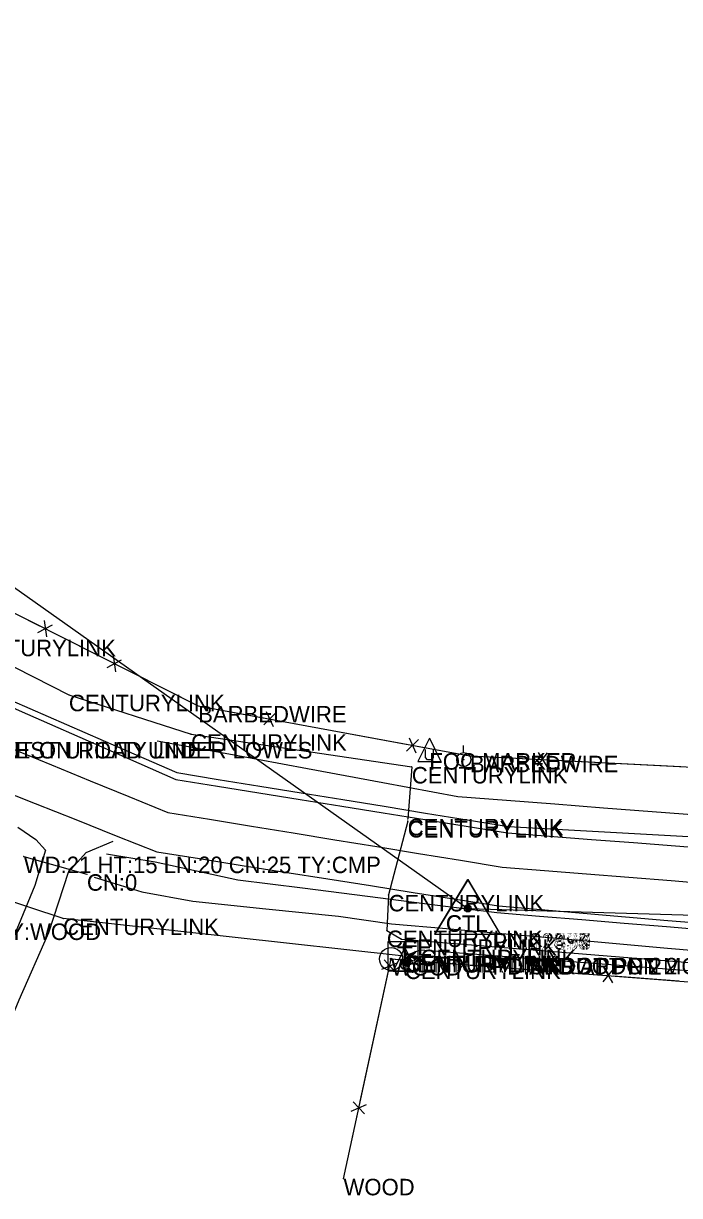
# Model space of a CAD drawing. Extents: x 675481 to 678499, y 212715 to 215285.
# Drawn here: x 675753.3 to 675952.1, y 214646.6 to 215001.7 of the extents above; entities that cross this region are included whole.
import ezdxf

# ---------------------------------------------------------------- set-up
doc = ezdxf.new("R2010")
doc.units = 0
for name, color, linetype in [('S_BASELINE', 7, 'Continuous'), ('S_DITCHLINE', 7, 'Continuous'), ('S_DRG_PT_SYM', 7, 'Continuous'), ('S_DRIVEWAY', 7, 'Continuous'), ('S_EDGE_PAVEMENT', 7, 'Continuous'), ('S_ELECTRIC_UTILITIES_ANNOT', 7, 'Continuous'), ('S_FENCE', 7, 'Continuous'), ('S_FENCE_ANNOT', 7, 'Continuous'), ('S_FIBER_OPTIC_CABLE', 7, 'Continuous'), ('S_FIBER_OPTIC_CABLE_ANNOT', 7, 'Continuous'), ('S_MSC_PT_SYM', 7, 'Continuous'), ('S_PAVEMENT_CROWN', 7, 'Continuous'), ('S_PRIMARY_CTL', 7, 'Continuous'), ('S_PRIMARY_CTL_ANNOT', 7, 'Continuous'), ('S_SHOULDER', 7, 'Continuous'), ('S_SIDE_DRAIN', 7, 'Continuous'), ('S_SIDE_DRAIN_ANNOT', 7, 'Continuous'), ('S_SURVEY_TEXT_ANNOT', 7, 'Continuous'), ('S_TELEPHONE_UTILITIES', 7, 'Continuous'), ('S_TELEPHONE_UTILITIES_ANNOT', 7, 'Continuous'), ('S_UNDERGROUND_CABLE', 7, 'Continuous'), ('S_UTILITY_POLE', 7, 'Continuous'), ('S_UTILITY_POLE_ANNOT', 7, 'Continuous'), ('S_UTL_PT_SYM', 7, 'Continuous')]:
    doc.layers.add(name, color=color, linetype=linetype)

msp = doc.modelspace()

# ---------------------------------------------------------------- linework, layer by layer
at = {"layer": 'S_BASELINE'}
for p, q in [((675509.19, 215001.71), (675887.93, 214733.6)), ((675887.93, 214733.6), (676879.32, 214703.75))]:
    msp.add_line(p, q, dxfattribs=at)
at = {"layer": 'S_DITCHLINE'}
for points in [[(675793.89, 214784.39), (675816.64, 214780.16), (675839.4, 214775.93), (675862.15, 214771.71), (675884.9, 214767.48), (675899.62, 214766.35), (675914.33, 214765.22), (675929.05, 214764.09), (675943.76, 214762.96), (675958.47, 214761.83)], [(675774.78, 214743.03), (675789.16, 214738.55), (675804.68, 214735.79), (675826.73, 214733.49), (675848.79, 214731.19), (675864.79, 214728.95), (675881.52, 214727.47), (675898.25, 214726), (675914.98, 214724.52), (675931.71, 214723.05), (675948.44, 214721.58), (675965.17, 214720.1)]]:
    msp.add_lwpolyline(points, dxfattribs=at)
at = {"layer": 'S_DRG_PT_SYM'}
for points in [[(675753.46, 214749.27), (675753.46, 214749.32), (675753.46, 214749.27), (675753.41, 214749.27), (675753.46, 214749.27), (675753.46, 214749.22), (675753.46, 214749.27), (675753.52, 214749.27)], [(675772.57, 214743.93), (675772.57, 214743.98), (675772.57, 214743.93), (675772.52, 214743.93), (675772.57, 214743.93), (675772.57, 214743.88), (675772.57, 214743.93), (675772.62, 214743.93)]]:
    msp.add_lwpolyline(points, dxfattribs=at)
at = {"layer": 'S_DRIVEWAY'}
for points in [[(675751.63, 214758.15), (675757.05, 214754.42), (675760.02, 214751.26), (675756.81, 214740.56), (675751.81, 214728.55), (675746.82, 214716.54), (675737.48, 214695.71), (675728.14, 214674.89)], [(675737.46, 214671.17), (675744.73, 214688.51), (675752, 214705.86), (675761.06, 214726.23), (675767, 214744.56), (675772.39, 214750.55), (675780.54, 214753.93)]]:
    msp.add_lwpolyline(points, dxfattribs=at)
at = {"layer": 'S_EDGE_PAVEMENT'}
for points in [[(675732.14, 214802.34), (675754.6, 214792.44), (675777.06, 214782.54), (675799.52, 214772.64), (675812.08, 214770.62), (675824.64, 214768.6), (675837.19, 214766.58), (675849.75, 214764.57), (675862.31, 214762.55), (675874.87, 214760.53), (675887.42, 214758.51), (675899.98, 214756.49), (675912.7, 214755.5), (675925.41, 214754.5), (675938.13, 214753.5), (675950.84, 214752.51), (675963.55, 214751.51)], [(675744.62, 214770.25), (675756.89, 214765.36), (675769.17, 214760.48), (675781.45, 214755.59), (675793.72, 214750.7), (675806.67, 214748.65), (675819.61, 214746.61), (675832.55, 214744.56), (675845.49, 214742.51), (675858.43, 214740.47), (675871.37, 214738.42), (675884.31, 214736.37), (675897.25, 214734.33), (675910.07, 214733.24), (675922.88, 214732.14), (675935.69, 214731.05), (675948.5, 214729.96), (675961.32, 214728.87)]]:
    msp.add_lwpolyline(points, dxfattribs=at)
at = {"layer": 'S_FENCE'}
for p, q in [((675701.08, 214848.07), (675806.27, 214794.91)), ((675757.75, 214817.14), (675762.16, 214819.5)), ((675759.6, 214820.79), (675760.31, 214815.84)), ((675778.66, 214806.57), (675783.07, 214808.93)), ((675780.51, 214810.23), (675781.22, 214805.28)), ((675806.27, 214794.91), (675888.58, 214779.82)), ((675826.13, 214789.19), (675829.69, 214792.7)), ((675826.87, 214793.22), (675828.95, 214788.67)), ((675869.4, 214781.26), (675872.96, 214784.77)), ((675870.14, 214785.29), (675872.22, 214780.74)), ((675888.58, 214779.82), (676003.88, 214773.95)), ((675909.02, 214776.73), (675912.09, 214780.68)), ((675909.22, 214780.82), (675911.88, 214776.59)), ((675850.29, 214651.65), (675864.7, 214718.25)), ((675861.94, 214715.19), (675866.55, 214717.12)), ((675865.94, 214714.32), (675862.55, 214717.99)), ((675864.7, 214718.25), (675996.97, 214708.14)), ((675885.05, 214714.64), (675888.22, 214718.51)), ((675885.36, 214718.72), (675887.9, 214714.42)), ((675928.91, 214711.29), (675932.08, 214715.15)), ((675929.22, 214715.37), (675931.77, 214711.07)), ((675852.64, 214672.18), (675857.25, 214674.12)), ((675856.64, 214671.32), (675853.24, 214674.98))]:
    msp.add_line(p, q, dxfattribs=at)
for points in [[(675722.49, 214837.25), (675758.17, 214819.22)], [(675761.24, 214817.67), (675779.08, 214808.65)], [(675782.65, 214806.85), (675806.27, 214794.91)], [(675806.27, 214794.91), (675825.94, 214791.31)], [(675829.88, 214790.58), (675869.22, 214783.37)], [(675872.59, 214782.75), (675888.58, 214779.82)], [(675888.58, 214779.82), (675908.56, 214778.81)], [(675912.55, 214778.6), (675952.49, 214776.57)], [(675864.55, 214717.56), (675864.7, 214718.25)], [(675864.7, 214718.25), (675884.64, 214716.73)], [(675888.62, 214716.42), (675928.5, 214713.37)], [(675855.36, 214675.1), (675863.82, 214714.2)], [(675931.92, 214713.11), (675951.86, 214711.59)], [(675850.29, 214651.65), (675854.52, 214671.2)]]:
    msp.add_lwpolyline(points, dxfattribs=at)
for radius in [3.49, 0.247, 0.0349]:
    msp.add_circle((675864.7, 214718.26), radius, dxfattribs=at)
at = {"layer": 'S_FIBER_OPTIC_CABLE'}
for p, q in [((675734.15, 214814.98), (675767.11, 214798.31)), ((675767.11, 214798.31), (675804.1, 214786.33)), ((675804.1, 214786.33), (675870.96, 214776.43)), ((675870.96, 214776.43), (675869.73, 214760.71)), ((675765.38, 214730.52), (675671.26, 214761.36)), ((675869.75, 214760.06), (675863.91, 214737.67)), ((675863.91, 214737.67), (675863.43, 214726.87)), ((675867.76, 214719.18), (675765.38, 214730.52)), ((675863.43, 214726.87), (675867.82, 214724.23)), ((675867.82, 214724.23), (675997.97, 214713.72)), ((675869.1, 214719.29), (675873.58, 214721.07)), ((675873.58, 214721.07), (675998.01, 214711.46))]:
    msp.add_line(p, q, dxfattribs=at)
at = {"layer": 'S_MSC_PT_SYM'}
for points in [[(675806.27, 214794.91), (675806.27, 214794.96), (675806.27, 214794.91), (675806.22, 214794.91), (675806.27, 214794.91), (675806.27, 214794.86), (675806.27, 214794.91), (675806.32, 214794.91)], [(675888.58, 214779.82), (675888.58, 214779.87), (675888.58, 214779.82), (675888.53, 214779.82), (675888.58, 214779.82), (675888.58, 214779.77), (675888.58, 214779.82), (675888.63, 214779.82)], [(675864.7, 214718.25), (675864.7, 214718.3), (675864.7, 214718.25), (675864.65, 214718.25), (675864.7, 214718.25), (675864.7, 214718.2), (675864.7, 214718.25), (675864.75, 214718.25)], [(675850.29, 214651.65), (675850.29, 214651.7), (675850.29, 214651.65), (675850.24, 214651.65), (675850.29, 214651.65), (675850.29, 214651.6), (675850.29, 214651.65), (675850.34, 214651.65)]]:
    msp.add_lwpolyline(points, dxfattribs=at)
at = {"layer": 'S_PAVEMENT_CROWN'}
msp.add_lwpolyline([(675750.05, 214781.92), (675761.8, 214777.1), (675773.56, 214772.27), (675785.31, 214767.45), (675797.07, 214762.63), (675809.73, 214760.57), (675822.39, 214758.5), (675835.04, 214756.44), (675847.7, 214754.37), (675860.36, 214752.31), (675873.02, 214750.24), (675885.68, 214748.18), (675898.34, 214746.12), (675911.13, 214745.09), (675923.93, 214744.06), (675936.72, 214743.03), (675949.52, 214742), (675962.31, 214740.96)], dxfattribs=at)
at = {"layer": 'S_PRIMARY_CTL'}
for p, q in [((675887.87, 214742.29), (675877.84, 214725.78)), ((675887.89, 214742.3), (675877.85, 214725.79)), ((675887.9, 214742.27), (675877.86, 214725.75)), ((675887.9, 214742.29), (675877.87, 214725.78)), ((675887.91, 214742.27), (675877.87, 214725.75)), ((675887.92, 214742.24), (675877.88, 214725.73)), ((675887.93, 214742.3), (675877.89, 214725.78)), ((675887.93, 214742.29), (675877.9, 214725.78)), ((675887.93, 214742.27), (675877.9, 214725.76)), ((675887.87, 214742.29), (675897.69, 214725.78)), ((675887.89, 214742.3), (675897.71, 214725.79)), ((675887.9, 214742.29), (675897.73, 214725.78)), ((675887.9, 214742.27), (675897.72, 214725.75)), ((675887.91, 214742.27), (675897.73, 214725.75)), ((675887.92, 214742.24), (675897.74, 214725.73)), ((675887.93, 214742.3), (675897.75, 214725.78)), ((675887.93, 214742.29), (675897.75, 214725.78)), ((675887.93, 214742.27), (675897.76, 214725.76)), ((675877.84, 214725.78), (675897.69, 214725.78)), ((675877.85, 214725.79), (675897.71, 214725.79)), ((675877.86, 214725.75), (675897.72, 214725.75)), ((675877.87, 214725.78), (675897.73, 214725.78)), ((675877.87, 214725.75), (675897.73, 214725.75)), ((675877.88, 214725.73), (675897.74, 214725.73)), ((675877.89, 214725.78), (675897.75, 214725.78)), ((675877.9, 214725.78), (675897.75, 214725.78)), ((675877.9, 214725.76), (675897.76, 214725.76))]:
    msp.add_line(p, q, dxfattribs=at)
for centre, radius in [((675887.87, 214733.59), 1.04), ((675887.89, 214733.6), 1.04), ((675887.9, 214733.57), 1.04), ((675887.9, 214733.59), 1.04), ((675887.91, 214733.57), 1.04), ((675887.92, 214733.54), 1.04), ((675887.93, 214733.6), 1.04), ((675887.93, 214733.59), 1.04), ((675887.93, 214733.57), 1.04), ((675887.87, 214733.59), 0.609), ((675887.89, 214733.6), 0.609), ((675887.9, 214733.57), 0.609), ((675887.9, 214733.59), 0.609), ((675887.91, 214733.57), 0.609), ((675887.92, 214733.54), 0.609), ((675887.93, 214733.6), 0.609), ((675887.93, 214733.59), 0.609), ((675887.93, 214733.57), 0.609), ((675887.87, 214733.59), 0.344), ((675887.89, 214733.6), 0.344), ((675887.9, 214733.57), 0.344), ((675887.9, 214733.59), 0.344), ((675887.91, 214733.57), 0.344), ((675887.92, 214733.54), 0.344), ((675887.93, 214733.6), 0.344), ((675887.93, 214733.59), 0.344), ((675887.93, 214733.57), 0.344)]:
    msp.add_circle(centre, radius, dxfattribs=at)
at = {"layer": 'S_SHOULDER'}
for points in [[(675732.93, 214803.88), (675755.23, 214794.15), (675777.52, 214784.43), (675799.81, 214774.71), (675812.37, 214772.67), (675824.93, 214770.63), (675837.49, 214768.59), (675850.05, 214766.55), (675862.6, 214764.51), (675875.16, 214762.47), (675887.72, 214760.43), (675900.28, 214758.39), (675912.98, 214757.68), (675925.69, 214756.96), (675938.39, 214756.24), (675951.1, 214755.53), (675963.8, 214754.81)], [(675778.46, 214750.11), (675793.23, 214747.66), (675805.75, 214744.96), (675818.28, 214742.27), (675837.9, 214739.78), (675857.52, 214737.3), (675877.14, 214734.81), (675896.76, 214732.33), (675909.6, 214731.26), (675922.44, 214730.19), (675935.27, 214729.12), (675948.11, 214728.06), (675960.95, 214726.99)]]:
    msp.add_lwpolyline(points, dxfattribs=at)
at = {"layer": 'S_SIDE_DRAIN'}
msp.add_line((675753.46, 214749.27), (675772.57, 214743.93), dxfattribs=at)
at = {"layer": 'S_TELEPHONE_UTILITIES'}
msp.add_lwpolyline([(675863.83, 214714.6), (675863.83, 214723.6), (675872.83, 214723.6), (675872.83, 214714.6)], close=True, dxfattribs=at)
at = {"layer": 'S_UNDERGROUND_CABLE'}
for p, q in [((675876.28, 214785.15), (675872.75, 214778.06)), ((675876.28, 214785.15), (675879.77, 214778.06)), ((675875.08, 214779.3), (675875.08, 214781.74)), ((675877.44, 214781.74), (675877.44, 214779.3)), ((675872.75, 214778.06), (675879.77, 214778.06)), ((675875.7, 214778.64), (675875.08, 214779.3)), ((675876.9, 214778.64), (675875.7, 214778.64)), ((675877.44, 214779.3), (675876.9, 214778.64)), ((675868.9, 214721.71), (675865.37, 214714.61)), ((675868.9, 214721.71), (675872.39, 214714.61)), ((675867.7, 214715.85), (675867.7, 214718.3)), ((675868.32, 214715.2), (675867.7, 214715.85)), ((675870.06, 214715.85), (675869.52, 214715.2)), ((675870.06, 214718.3), (675870.06, 214715.85)), ((675865.37, 214714.61), (675872.39, 214714.61)), ((675869.52, 214715.2), (675868.32, 214715.2))]:
    msp.add_line(p, q, dxfattribs=at)
at = {"layer": 'S_UTILITY_POLE'}
msp.add_line((675886.6, 214780.81), (675886.6, 214782.91), dxfattribs=at)
msp.add_circle((675886.72, 214778.66), 2.13, dxfattribs=at)
at = {"layer": 'S_UTL_PT_SYM'}
for points in [[(675767.11, 214798.31), (675767.11, 214798.36), (675767.11, 214798.31), (675767.06, 214798.31), (675767.11, 214798.31), (675767.11, 214798.26), (675767.11, 214798.31), (675767.16, 214798.31)], [(675804.1, 214786.33), (675804.1, 214786.38), (675804.1, 214786.33), (675804.05, 214786.33), (675804.1, 214786.33), (675804.1, 214786.28), (675804.1, 214786.33), (675804.15, 214786.33)], [(675870.96, 214776.43), (675870.96, 214776.48), (675870.96, 214776.43), (675870.91, 214776.43), (675870.96, 214776.43), (675870.96, 214776.38), (675870.96, 214776.43), (675871.01, 214776.43)], [(675886.72, 214778.66), (675886.72, 214778.71), (675886.72, 214778.66), (675886.67, 214778.66), (675886.72, 214778.66), (675886.72, 214778.62), (675886.72, 214778.66), (675886.78, 214778.66)], [(675869.73, 214760.71), (675869.73, 214760.76), (675869.73, 214760.71), (675869.68, 214760.71), (675869.73, 214760.71), (675869.73, 214760.66), (675869.73, 214760.71), (675869.78, 214760.71)], [(675869.75, 214760.06), (675869.75, 214760.11), (675869.75, 214760.06), (675869.7, 214760.06), (675869.75, 214760.06), (675869.75, 214760.01), (675869.75, 214760.06), (675869.8, 214760.06)], [(675863.91, 214737.67), (675863.91, 214737.71), (675863.91, 214737.67), (675863.86, 214737.67), (675863.91, 214737.67), (675863.91, 214737.62), (675863.91, 214737.67), (675863.96, 214737.67)], [(675765.38, 214730.52), (675765.38, 214730.57), (675765.38, 214730.52), (675765.33, 214730.52), (675765.38, 214730.52), (675765.38, 214730.47), (675765.38, 214730.52), (675765.43, 214730.52)], [(675863.43, 214726.87), (675863.43, 214726.92), (675863.43, 214726.87), (675863.38, 214726.87), (675863.43, 214726.87), (675863.43, 214726.82), (675863.43, 214726.87), (675863.48, 214726.87)], [(675867.82, 214724.23), (675867.82, 214724.28), (675867.82, 214724.23), (675867.77, 214724.23), (675867.82, 214724.23), (675867.82, 214724.18), (675867.82, 214724.23), (675867.87, 214724.23)], [(675867.76, 214719.18), (675867.76, 214719.23), (675867.76, 214719.18), (675867.71, 214719.18), (675867.76, 214719.18), (675867.76, 214719.13), (675867.76, 214719.18), (675867.81, 214719.18)], [(675869.1, 214719.29), (675869.1, 214719.34), (675869.1, 214719.29), (675869.05, 214719.29), (675869.1, 214719.29), (675869.1, 214719.24), (675869.1, 214719.29), (675869.15, 214719.29)], [(675873.58, 214721.07), (675873.58, 214721.12), (675873.58, 214721.07), (675873.53, 214721.07), (675873.58, 214721.07), (675873.58, 214721.02), (675873.58, 214721.07), (675873.63, 214721.07)]]:
    msp.add_lwpolyline(points, dxfattribs=at)

# ---------------------------------------------------------------- texts
at = {"layer": 'S_ELECTRIC_UTILITIES_ANNOT'}
msp.add_text('LOWEST UTILITY LINE', height=5, dxfattribs=at).set_placement((675735.73, 214779.01))
at = {"layer": 'S_FENCE_ANNOT'}
for s, p in [('BARBEDWIRE', (675806.27, 214789.91)), ('BARBEDWIRE', (675888.58, 214774.82)), ('TY:WOOD', (675744.93, 214724.01)), ('WOOD', (675864.7, 214713.26)), ('WOOD', (675864.7, 214713.25)), ('WOOD', (675850.29, 214646.65))]:
    msp.add_text(s, height=5, dxfattribs=at).set_placement(p)
at = {"layer": 'S_FIBER_OPTIC_CABLE_ANNOT'}
for p in [(675734.15, 214809.98), (675767.11, 214793.31), (675804.1, 214781.33), (675870.96, 214771.43), (675869.73, 214755.71), (675869.75, 214755.06), (675863.91, 214732.67), (675765.38, 214725.52), (675863.43, 214721.87), (675867.82, 214719.23), (675867.76, 214714.18), (675869.1, 214714.29), (675873.58, 214716.07)]:
    msp.add_text('CENTURYLINK', height=5, dxfattribs=at).set_placement(p)
at = {"layer": 'S_PRIMARY_CTL'}
for p in [(675881.28, 214726.51), (675881.3, 214726.52), (675881.31, 214726.49), (675881.32, 214726.52), (675881.32, 214726.49), (675881.33, 214726.47), (675881.34, 214726.52), (675881.34, 214726.52), (675881.35, 214726.49)]:
    msp.add_text('CTL', height=5, rotation=360, dxfattribs=at).set_placement(p)
at = {"layer": 'S_PRIMARY_CTL_ANNOT'}
for s, p in [('PN:11514', (675895.37, 214721.09)), ('PN:11492', (675895.39, 214721.1)), ('PN:11076', (675895.4, 214721.09)), ('PN:11112', (675895.4, 214721.07)), ('PN:11113', (675895.41, 214721.07)), ('PN:11516', (675895.42, 214721.04)), ('PN:2', (675895.43, 214721.1)), ('PN:11030', (675895.43, 214721.09)), ('PN:12877', (675895.44, 214721.07)), ('PD:ARRDOT PN 2', (675895.37, 214713.59)), ('PD:ARDOT PN 2', (675895.39, 214713.6)), ('PD:ARDOT PN 2', (675895.4, 214713.59)), ('PD:ARDOT PN 2', (675895.4, 214713.57)), ('PD:ARDOT PN 2', (675895.41, 214713.57)), ('PD:ARDOT PN 2', (675895.42, 214713.54)), ('PD:STD ARDOT MON STAMPED PN:2', (675895.43, 214713.6)), ('PD:ARDOT PN 2', (675895.43, 214713.59)), ('PD:ARDOT PN 2', (675895.44, 214713.57))]:
    msp.add_text(s, height=5, dxfattribs=at).set_placement(p)
at = {"layer": 'S_SIDE_DRAIN_ANNOT'}
for s, p in [('WD:21 HT:15 LN:20 CN:25 TY:CMP', (675753.46, 214744.27)), ('CN:0', (675772.57, 214738.93))]:
    msp.add_text(s, height=5, dxfattribs=at).set_placement(p)
at = {"layer": 'S_SURVEY_TEXT_ANNOT'}
msp.add_text('POINT ON ROAD UNDER LOWES', height=5, dxfattribs=at).set_placement((675735.73, 214779.01))
at = {"layer": 'S_TELEPHONE_UTILITIES'}
msp.add_text('T', height=6, rotation=360, dxfattribs=at).set_placement((675866.4, 214716.1))
at = {"layer": 'S_TELEPHONE_UTILITIES_ANNOT'}
msp.add_text('CENTURYLINK', height=5, dxfattribs=at).set_placement((675868.56, 214714.12))
at = {"layer": 'S_UTILITY_POLE_ANNOT'}
for s, p in [('FOC MARKER', (675876.28, 214775.62)), ('CENTURYLINK', (675868.9, 214712.17))]:
    msp.add_text(s, height=5, dxfattribs=at).set_placement(p)

doc.saveas('drawing.dxf')
